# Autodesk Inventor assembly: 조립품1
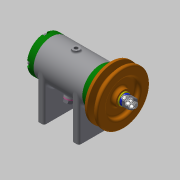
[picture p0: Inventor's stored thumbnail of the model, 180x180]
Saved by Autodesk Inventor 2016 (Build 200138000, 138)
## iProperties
Created: 2020-07
Part Number: 조립품1
Material: 일반
Document SubType Name: Assembly
Designer: 605-04
Author: 605-04
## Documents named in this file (14)
- C:\Users\605-04\Desktop\700706V1013\조립품1.iam
- C:\Users\605-04\Desktop\700706V1013\본체.ipt
- C:\Users\605-04\Desktop\700706V1013\뒤커버.ipt
- C:\Users\605-04\Desktop\700706V1013\앞커버.ipt
- C:\Users\605-04\Desktop\700706V1013\베어링 6002.ipt
- C:\Users\605-04\Desktop\700706V1013\축.ipt
- C:\Users\605-04\Desktop\700706V1013\키 3x3x12.ipt
- C:\Users\605-04\Desktop\700706V1013\V벨트풀리.ipt
- C:\Users\605-04\Desktop\700706V1013\와셔 8x17.ipt
- C:\Users\605-04\Desktop\700706V1013\스프링와셔 8.ipt
- C:\Users\605-04\Desktop\700706V1013\너트 M8.ipt
- C:\Users\605-04\Desktop\700706V1013\와셔 6x11.5.ipt
- C:\Users\605-04\Desktop\700706V1013\볼트 M6x8.ipt
- C:\Users\605-04\Desktop\700706V1013\볼트 M4x12.ipt
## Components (1 placed, 1 different names)
1. V벨트풀리:1
